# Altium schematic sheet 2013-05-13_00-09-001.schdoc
size 227 x 165 mm; SheetNumber: 1; SheetTotal: 1
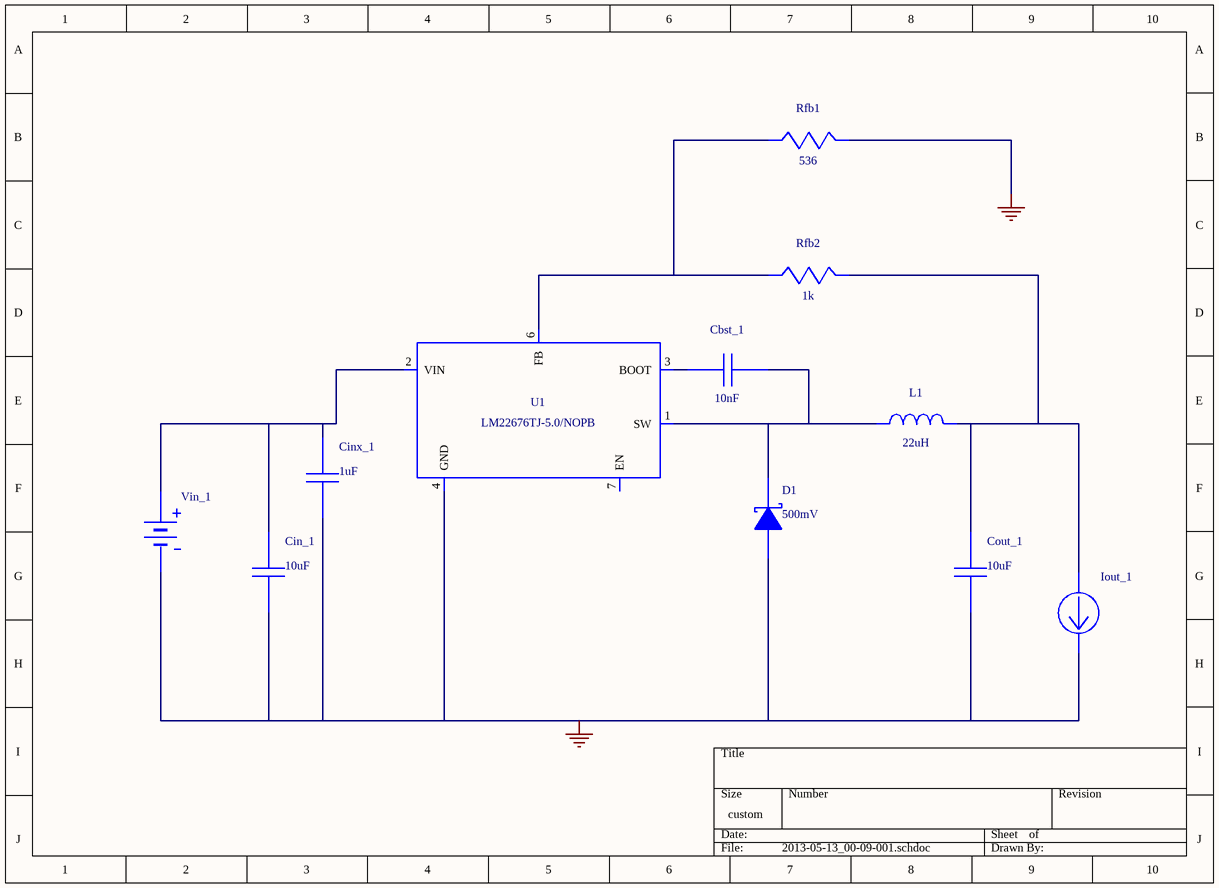
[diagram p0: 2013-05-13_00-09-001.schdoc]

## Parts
Cbst_1  value 10nF  (hidden comment: C0805C103K5RACTU)
Cin_1  value 10uF  (hidden comment: C5750X7R1H106M)
Cinx_1  value 1uF  (hidden comment: GMK212B7105KG-T)
Cout_1  value 10uF  (hidden comment: C3225X5R1E106K)
D1  value 500mV  (hidden comment: B240A-13-F)
Iout_1  WB_CURRENT_LOAD  (value not drawn)
L1  value 22uH  (hidden comment: XAL6060-223MEB)
Rfb1  value 536  (hidden comment: CRCW0805536RFKEA)
Rfb2  value 1k  (hidden comment: CRCW08051K00FKEA)
U1  LM22676TJ-5.0/NOPB
Vin_1  WB_BATTERY  (value not drawn)

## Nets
0: Cin_1.2 Cinx_1.2 Cout_1.2 D1.2(A) Iout_1.2(-) Rfb1.1 U1.4(GND) U1.8(DAP) Vin_1.2(-)
NetCbst_1_1: Cbst_1.1 D1.1(K) L1.2 U1.1(SW)
NetCbst_1_2: Cbst_1.2 U1.3(BOOT)
NetCin_1_1: Cin_1.1 Cinx_1.1 U1.2(VIN) Vin_1.1(+)
NetCout_1_1: Cout_1.1 Iout_1.1(+) L1.1 Rfb2.1
NetRfb1_2: Rfb1.2 Rfb2.2 U1.6(FB)

Not connected (* = marked no-connect by the designer): U1 7(EN)

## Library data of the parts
Cbst_1 = C0805C103K5RACTU: Manufacturer Name: Kemet
Cin_1 = C5750X7R1H106M: Manufacturer Name: TDK
Cinx_1 = GMK212B7105KG-T: Manufacturer Name: Taiyo Yuden
Cout_1 = C3225X5R1E106K: Manufacturer Name: TDK
D1 = B240A-13-F: Manufacturer Name: Diodes Inc.
Iout_1 = WB_CURRENT_LOAD: Value: UNLISTED
L1 = XAL6060-223MEB: Manufacturer Name: Coilcraft
Rfb1 = CRCW0805536RFKEA: Manufacturer Name: Vishay-Dale
Rfb2 = CRCW08051K00FKEA: Manufacturer Name: Vishay-Dale
U1 = LM22676TJ-5.0/NOPB: LM22676TJ-5.0/NO; Manufacturer Name: Texas Instruments; Value: UNLISTED
Vin_1 = WB_BATTERY: Value: UNLISTED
